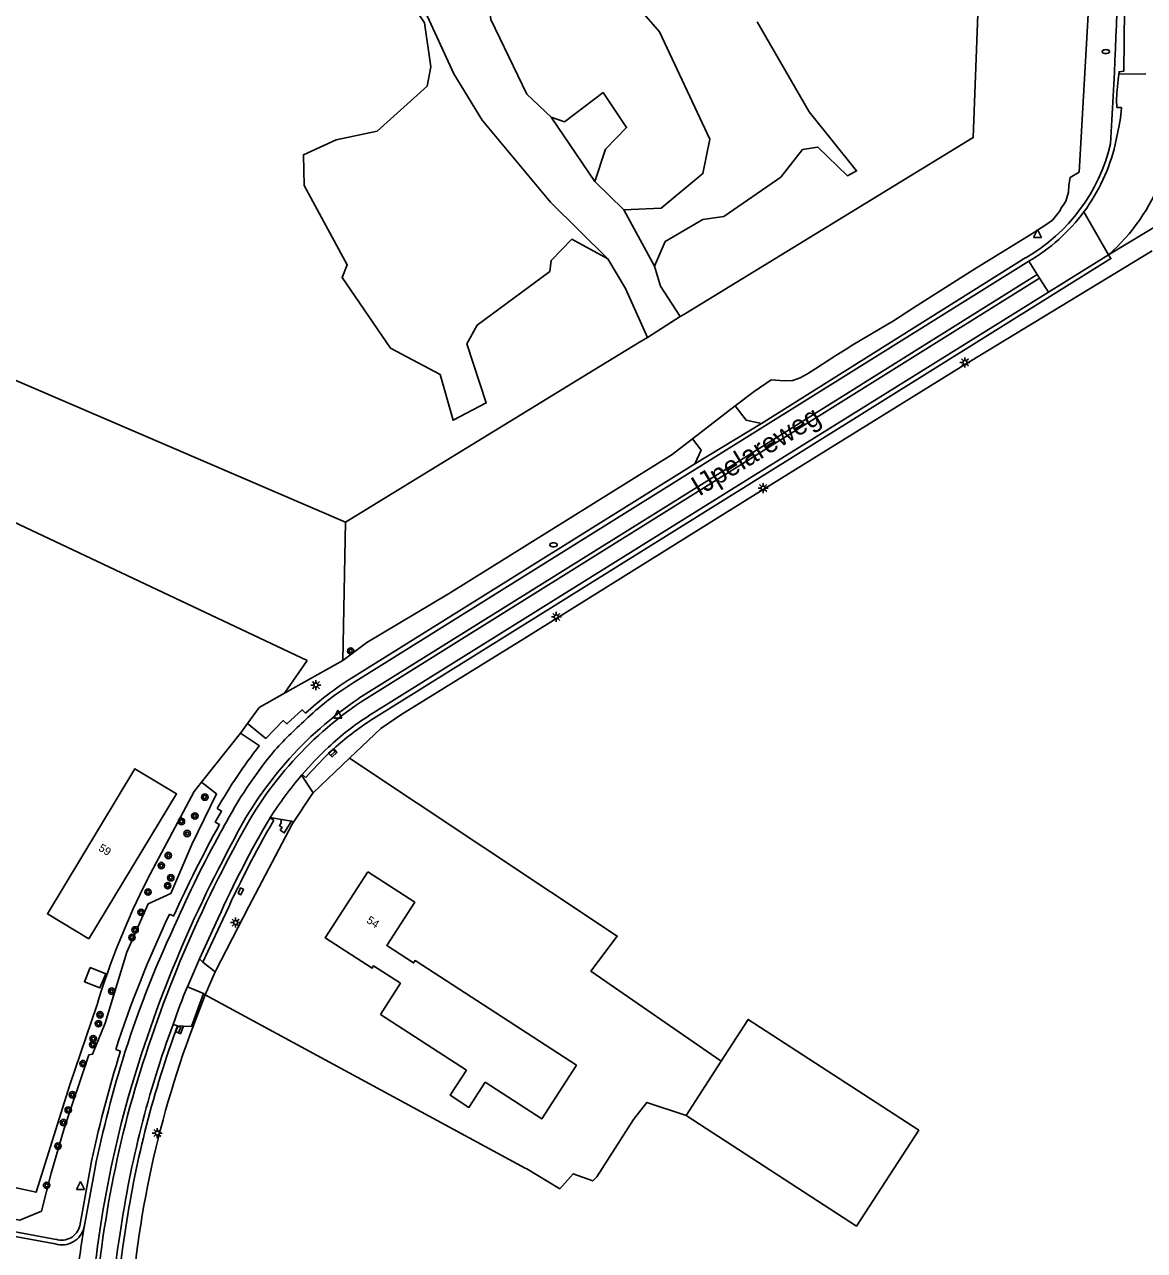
# Model space of a CAD drawing. Extents: x 130998 to 133001, y 398999 to 403002.
# Drawn here: x 132708.1 to 132848, y 400223.9 to 400377.1 of the extents above; entities that cross this region are included whole.
import ezdxf

# ---------------------------------------------------------------- set-up
doc = ezdxf.new("R2010")
doc.units = 0
for name, color, linetype in [('gg-afsc-draadraster', 7, 'Continuous'), ('gg-afsc-hekwerk', 7, 'Continuous'), ('gg-anno-huisnummerreeks BGT', 7, 'Continuous'), ('gg-anno-openbare ruimte label', 7, 'Continuous'), ('gg-bbg-bijgebouw', 7, 'Continuous'), ('gg-bbg-hoofdgebouw', 7, 'Continuous'), ('gg-bbg-lage trafo', 7, 'Continuous'), ('gg-knt-bronhoudergrens', 7, 'Continuous'), ('gg-knt-verharding', 7, 'Continuous'), ('gg-knt-verharding nz', 7, 'Continuous'), ('gt-grn-groengrens', 7, 'Continuous'), ('gt-grn-groengrens NZ', 7, 'Continuous'), ('gt-grn-weggrens', 7, 'Continuous'), ('gt-symb-boom', 7, 'Continuous'), ('gt-symb-brandkraan', 7, 'Continuous'), ('gt-symb-kolk center center', 7, 'Continuous'), ('gt-symb-lichtmast', 7, 'Continuous'), ('gt-symb-waterafsluiter', 7, 'Continuous'), ('gx-grn-maaiveld', 7, 'Continuous')]:
    doc.layers.add(name, color=color, linetype=linetype)

# ---------------------------------------------------------------- blocks, each defined once
blk = doc.blocks.new('gt0-BR')
at = {"layer": 'gt-symb-brandkraan'}
for centre, radius, start, end in [((-0.24, 0), 0.206, 107.5669, 252.4331), ((0.6, -2.66), 3, 106.892, 107.5669), ((0, -0.69), 0.938, 73.108, 106.892), ((-0.6, -2.66), 3, 72.4331, 73.108), ((0.24, 0), 0.206, 287.567, 72.4331), ((0.6, 2.66), 3, 252.4331, 253.108), ((0, 0.69), 0.938, 253.108, 286.8921), ((-0.6, 2.66), 3, 286.8921, 287.567)]:
    blk.add_arc(centre, radius, start, end, dxfattribs=at)
blk = doc.blocks.new('gt0-WAFSL')
at = {"layer": 'gt-symb-waterafsluiter'}
for p, q in [((-0.5, -0.33), (0, 0.67)), ((0, 0.67), (0.5, -0.33)), ((0.5, -0.33), (-0.5, -0.33))]:
    blk.add_line(p, q, dxfattribs=at)
blk = doc.blocks.new('gt0-LMAST')
at = {"layer": 'gt-symb-lichtmast'}
for p, q in [((-0.18, 0.17), (-0.45, 0.44)), ((-0.01, 0.25), (-0.01, 0.62)), ((0.17, 0.17), (0.44, 0.44)), ((-0.26, 0), (-0.63, 0)), ((-0.18, -0.18), (-0.45, -0.45)), ((-0.01, -0.25), (-0.01, -0.63)), ((0.44, -0.45), (0.17, -0.18)), ((0.24, 0), (0.62, 0))]:
    blk.add_line(p, q, dxfattribs=at)
blk.add_circle((-0.01, 0), 0.25, dxfattribs=at)
blk = doc.blocks.new('gt0-BOOM')
at = {"layer": 'gt-symb-boom'}
for radius in [0.4, 0.2]:
    blk.add_circle((0, 0), radius, dxfattribs=at)
blk = doc.blocks.new('gt0-KOLKCC')
at = {"layer": 'gt-symb-kolk center center'}
blk.add_lwpolyline([(-0.38, 0.2), (0.38, 0.2), (0.38, -0.2), (-0.38, -0.2)], close=True, dxfattribs=at)

msp = doc.modelspace()

# ---------------------------------------------------------------- linework, layer by layer
at = {"layer": 'gg-afsc-draadraster'}
for p, q in [((132723.58, 400267.23), (132720.93, 400261.2)), ((132730.7, 400255.89), (132770.67, 400234.22))]:
    msp.add_line(p, q, dxfattribs=at)
msp.add_lwpolyline([(132716.16, 400248.4), (132713.1, 400239.2), (132711.45, 400233.59)], dxfattribs=at)
at = {"layer": 'gg-afsc-hekwerk'}
for p, q in [((132790.02, 400340.59), (132790.44, 400340.85)), ((132790.44, 400340.85), (132790.68, 400341)), ((132785.91, 400338), (132790.02, 400340.59)), ((132784.92, 400337.39), (132785.91, 400338)), ((132748.21, 400314.9), (132747.89, 400297.62)), ((132747.89, 400297.62), (132740.6, 400293.54)), ((132735.09, 400288.58), (132730.23, 400282.43)), ((132736, 400289.76), (132735.09, 400288.58)), ((132744.2, 400281.1), (132748.73, 400285.43)), ((132744.2, 400281.1), (132748.73, 400285.43)), ((132741.57, 400277.2), (132741.72, 400277.43)), ((132730.7, 400255.89), (132731.95, 400258.77)), ((132731.95, 400258.77), (132731.98, 400258.82)), ((132731.95, 400258.77), (132731.98, 400258.82)), ((132729.16, 400251.86), (132730.7, 400255.89))]:
    msp.add_line(p, q, dxfattribs=at)
for points in [[(132790.68, 400341), (132826.6, 400362.96), (132827.23, 400380.57), (132827.91, 400408.15), (132828.73, 400450.46), (132829.65, 400488.45), (132829.78, 400500)], [(132304.6, 400411.08), (132314.42, 400407.28), (132377.15, 400382.53), (132500, 400333.94), (132615.12, 400288.56), (132631.4, 400323.33), (132647.49, 400358.16), (132670.06, 400348.42), (132709.01, 400331.76), (132748.21, 400314.9)], [(132748.73, 400285.43), (132752.61, 400289.13), (132755.12, 400290.84), (132770.59, 400300.42), (132798.51, 400317.83), (132825.1, 400334.33), (132848.92, 400348.8)], [(132748.73, 400285.43), (132752.61, 400289.13), (132755.12, 400290.84), (132770.59, 400300.42), (132798.51, 400317.83), (132825.1, 400334.33), (132848.92, 400348.8)], [(132748.21, 400314.9), (132779.25, 400333.95), (132784.92, 400337.39)], [(132740.6, 400293.54), (132737.44, 400291.77), (132736, 400289.76)], [(132730.23, 400282.43), (132729.32, 400281.28), (132723.54, 400270.39)], [(132741.72, 400277.43), (132744.02, 400280.92), (132744.2, 400281.1)], [(132731.98, 400258.82), (132736.15, 400266.9), (132741.57, 400277.2)], [(132731.98, 400258.82), (132736.15, 400266.9), (132741.57, 400277.2)], [(132658.24, 400242.36), (132709.58, 400231.22), (132713.79, 400244.64), (132717.15, 400254.53)]]:
    msp.add_lwpolyline(points, dxfattribs=at)
for centre, radius, start, end in [((132810.4, 400226.22), 97.45, 153.0479, 163.1141), ((132846.27, 400207.76), 125.13, 159.3647, 177.2216)]:
    msp.add_arc(centre, radius, start, end, dxfattribs=at)
at = {"layer": 'gg-bbg-bijgebouw'}
msp.add_line((132790.75, 400240.8), (132795.13, 400247.58), dxfattribs=at)
msp.add_lwpolyline([(132795.13, 400247.58), (132798.5, 400252.81), (132819.8, 400238.97), (132812.01, 400226.99), (132790.75, 400240.8)], dxfattribs=at)
at = {"layer": 'gg-bbg-hoofdgebouw'}
msp.add_line((132763.31, 400246.49), (132752.57, 400253.44), dxfattribs=at)
for points in [[(132716.17, 400262.86), (132727.1, 400280.99), (132721.93, 400284.11), (132711.01, 400265.98), (132716.17, 400262.86)], [(132751, 400271.26), (132745.66, 400263.01), (132751.54, 400259.21), (132751.72, 400259.49), (132755.08, 400257.32), (132752.57, 400253.44)], [(132751, 400271.26), (132756.87, 400267.45), (132753.37, 400262.05), (132756.72, 400259.87), (132756.91, 400260.16), (132777.04, 400247.09), (132772.71, 400240.39), (132765.66, 400244.96)], [(132763.31, 400246.49), (132761.28, 400243.35), (132763.62, 400241.82), (132765.66, 400244.96)]]:
    msp.add_lwpolyline(points, dxfattribs=at)
at = {"layer": 'gg-bbg-lage trafo'}
msp.add_lwpolyline([(132716.35, 400259.29), (132718.28, 400258.51), (132717.56, 400256.74), (132715.63, 400257.52), (132716.35, 400259.29)], dxfattribs=at)
at = {"layer": 'gg-knt-bronhoudergrens'}
msp.add_lwpolyline([(132795.13, 400247.58), (132778.84, 400258.84), (132782.15, 400263.21), (132748.73, 400285.43)], dxfattribs=at)
at = {"layer": 'gg-knt-verharding'}
for p, q in [((132779.36, 400357.46), (132773.9, 400365.51)), ((132782.98, 400353.94), (132779.36, 400357.46)), ((132786.8, 400346.9), (132782.98, 400353.94)), ((132835.99, 400343.63), (132843.49, 400348.29)), ((132749.16, 400294.84), (132833.52, 400347.5)), ((132800.17, 400327.24), (132833.15, 400347.96)), ((132791.82, 400322.21), (132800.17, 400327.24)), ((132748.95, 400295.42), (132791.82, 400322.21)), ((132737.46, 400286.99), (132735.09, 400288.58)), ((132746.76, 400286.62), (132746.1, 400286.01)), ((132742.72, 400283.3), (132742.79, 400283.39)), ((132744.2, 400281.1), (132742.72, 400283.3)), ((132742.79, 400283.39), (132743.24, 400283.01)), ((132738.8, 400277.98), (132738.83, 400278.05)), ((132739.28, 400277.7), (132738.8, 400277.98)), ((132738.83, 400278.05), (132740.24, 400277.8)), ((132740.24, 400277.8), (132741.46, 400277.59)), ((132741.46, 400277.59), (132741.72, 400277.43)), ((132726.23, 400265.94), (132726.77, 400265.69)), ((132729.97, 400260.36), (132732.32, 400265.44)), ((132730.42, 400259.98), (132732.91, 400265.27)), ((132729.97, 400260.36), (132730.42, 400259.98)), ((132731.95, 400258.77), (132730.42, 400259.98)), ((132730.5, 400256.05), (132728.48, 400256.9)), ((132730.5, 400256.05), (132730.7, 400255.89)), ((132726.99, 400251.28), (132727.26, 400251.99)), ((132727.26, 400251.99), (132728, 400251.95)), ((132720.13, 400248.84), (132719.54, 400249.05)), ((132715.05, 400227.01), (132716.32, 400234.16)), ((132715.57, 400226.86), (132716.91, 400234.08)), ((132702.2, 400226.57), (132711.97, 400224.76))]:
    msp.add_line(p, q, dxfattribs=at)
for points in [[(132844.77, 400370.89), (132844.8, 400371.18), (132845.39, 400371.24), (132845.8, 400409.64), (132847.82, 400515.05)], [(132780.99, 400347.81), (132773.82, 400354.88), (132765.3, 400365.12), (132761.74, 400370.9), (132757.25, 400380.75), (132752.34, 400384.68), (132746.8, 400386.99), (132736.8, 400389.8), (132723.69, 400394.1), (132717.48, 400395.57), (132710.13, 400395.59)], [(132773.9, 400365.51), (132770.86, 400368.38), (132766.35, 400377.69), (132765.77, 400382.6)], [(132844.31, 400362.08), (132844.81, 400364.46), (132844.97, 400365.39), (132845.08, 400366.26), (132845.1, 400366.64), (132845.07, 400366.71), (132844.98, 400366.73), (132844.6, 400366.7), (132844.53, 400366.74), (132844.51, 400366.78), (132844.5, 400367.6), (132844.53, 400368.49), (132844.68, 400370.17), (132844.77, 400370.89)], [(132843.49, 400348.29), (132853.13, 400354.14), (132856.45, 400356.17)], [(132751.38, 400290.18), (132798.89, 400319.85), (132843.78, 400347.85), (132843.49, 400348.29)], [(132785.91, 400338), (132783.16, 400344.12), (132780.99, 400347.81)], [(132790.02, 400340.59), (132787.53, 400344.39), (132786.8, 400346.9)], [(132751.08, 400290.71), (132798.61, 400320.39), (132835.99, 400343.63)], [(132800.17, 400327.24), (132798.24, 400327.67), (132796.89, 400329.43)], [(132791.82, 400322.21), (132792.61, 400323.93), (132791.54, 400325.32)], [(132736, 400289.76), (132738.26, 400287.91), (132739.34, 400289.04), (132740.45, 400290.14), (132740.89, 400289.72), (132742.82, 400291.49), (132743.21, 400291.05)], [(132746.1, 400286.01), (132746.54, 400285.59), (132747.14, 400286.15), (132746.76, 400286.62)], [(132732.48, 400277.16), (132731.95, 400277.46), (132732.75, 400278.84), (132732.21, 400279.14)], [(132740.24, 400277.8), (132740.13, 400277.63), (132740.18, 400277.51), (132740.18, 400277.35), (132739.96, 400277), (132740.3, 400276.77), (132740.08, 400276.45), (132740.58, 400276.11), (132741.46, 400277.59)], [(132728.48, 400256.9), (132729.24, 400258.63), (132729.97, 400260.36)], [(132728, 400251.95), (132728.97, 400251.91), (132730.5, 400256.05)], [(132726.99, 400251.28), (132727.61, 400251.01), (132728, 400251.95)], [(132702.2, 400226.57), (132702.29, 400227.15), (132712.08, 400225.34)]]:
    msp.add_lwpolyline(points, dxfattribs=at)
for centre, radius, start, end in [((132011.1, 400411.9), 834.11, 356.58308, 359.85087), ((132822.01, 400367.29), 22.32, 299.9574, 346.7694), ((132821.99, 400367.32), 22.93, 323.4782, 346.7735), ((132821.99, 400367.33), 22.93, 300.1729, 323.4713), ((132770.84, 400260.68), 41.06, 122.2136, 132.289), ((132768.53, 400263.74), 36.64, 121.9229, 133.0291), ((132787.58, 400241.74), 65.73, 132.0758, 137.1598), ((132767.9, 400264.03), 31.53, 122.2292, 133.7821), ((132768.62, 400263.01), 32.17, 122.3957, 132.8014), ((132787.87, 400247.6), 63.98, 141.9938, 150.4681), ((132783.57, 400250.07), 57.22, 140.5574, 152.0901), ((132777.8, 400252.9), 46.42, 133.0914, 138.9434), ((132777.52, 400253.22), 45.41, 133.7711, 139.0042), ((132782.13, 400250), 51.59, 139.8035, 147.0636), ((132848.2, 400213.51), 126.99, 149.4898, 155.8627), ((132871.92, 400200.47), 159.14, 151.1896, 155.8043), ((132843.71, 400214.5), 127.06, 150.6064, 156.3757), ((132850.42, 400212.86), 128.67, 149.7371, 155.963), ((132855.08, 400205.14), 142.48, 154.7376, 162.0496), ((132847.66, 400208.1), 133.31, 154.5357, 162.2664), ((132788.35, 400231.55), 65.01, 157.046, 161.4994), ((132846.81, 400207.83), 128.04, 159.7353, 171.7965), ((132845.95, 400208.17), 126.54, 160.0794, 171.878), ((132862.12, 400204.22), 148.84, 162.554, 168.395), ((132870.28, 400202.29), 156.64, 162.7624, 168.2892), ((132712.8, 400227.48), 2.84, 252.9691, 347.3282), ((132712.77, 400227.59), 2.35, 252.9406, 345.6464), ((132843.92, 400206.16), 125.44, 170.8555, 185.7776), ((132842.38, 400206.18), 123.31, 170.7274, 182.7238)]:
    msp.add_arc(centre, radius, start, end, dxfattribs=at)
at = {"layer": 'gg-knt-verharding nz'}
for p, q in [((132834.57, 400345.86), (132834.85, 400345.41)), ((132726.7, 400252.18), (132727.26, 400251.99))]:
    msp.add_line(p, q, dxfattribs=at)
for points in [[(132749.89, 400292.92), (132797.19, 400322.47), (132834.57, 400345.86)], [(132834.85, 400345.41), (132797.48, 400322.02), (132750.19, 400292.49)]]:
    msp.add_lwpolyline(points, dxfattribs=at)
for centre, radius, start, end in [((132827.31, 400366.53), 24.38, 311.5685, 6.4473), ((132776.03, 400254.03), 46.85, 123.9081, 153.8904), ((132776.25, 400253.87), 46.59, 124.0074, 153.7963), ((132871.78, 400200.13), 156.68, 151.6016, 164.9244), ((132870.28, 400200.7), 154.56, 151.5027, 164.9661), ((132857.29, 400205.41), 141.32, 165.4603, 179.9283), ((132857.43, 400205.38), 140.94, 165.4481, 179.9129), ((132826.12, 400208.51), 112.06, 170.5751, 174.7636)]:
    msp.add_arc(centre, radius, start, end, dxfattribs=at)
at = {"layer": 'gt-grn-groengrens'}
for p, q in [((132841.53, 400389.22), (132839.83, 400358.63)), ((132775.56, 400364.91), (132773.9, 400365.51)), ((132787.62, 400354.13), (132782.98, 400353.94)), ((132747.89, 400297.62), (132750.89, 400299.88)), ((132740.6, 400293.54), (132743.45, 400297.66))]:
    msp.add_line(p, q, dxfattribs=at)
for points in [[(132787.62, 400354.13), (132792.84, 400358.46), (132793.71, 400362.74), (132787.41, 400376.16), (132778.8, 400386.1), (132776.02, 400386.74), (132772.19, 400385.49), (132769.8, 400383.73)], [(132750.83, 400381.61), (132755.79, 400380.79), (132758.1, 400377.27), (132758.87, 400371.81), (132758.41, 400369.36), (132752.16, 400363.75), (132747.06, 400362.66), (132742.96, 400360.81), (132743.05, 400356.96), (132748.44, 400347.08), (132747.8, 400345.49), (132753.82, 400336.66), (132760.04, 400333.37), (132761.65, 400327.65), (132765.8, 400329.82), (132763.36, 400337.19), (132764.64, 400339.53), (132773.71, 400346.22), (132773.89, 400347.58), (132776.46, 400350.25), (132780.99, 400347.81)], [(132786.8, 400346.9), (132788.15, 400349.96), (132792.84, 400352.74), (132795.44, 400353.08), (132802.58, 400358.02), (132805.28, 400361.46), (132807.2, 400361.77), (132810.9, 400358.19), (132812.03, 400358.78), (132806.09, 400366.17), (132799.6, 400377.39)], [(132779.36, 400357.46), (132780.7, 400361.49), (132783.32, 400364.2), (132780.38, 400368.57), (132775.56, 400364.91)], [(132839.83, 400358.63), (132838.7, 400357.98), (132838.51, 400357.02), (132838.48, 400356.13), (132838.27, 400355.43), (132838.17, 400355.03), (132837.87, 400354.54), (132837.59, 400354.17), (132837.44, 400353.83), (132836.55, 400352.7), (132835.89, 400352.22), (132835.07, 400351.66), (132834.23, 400351.12), (132833.38, 400350.59), (132829.57, 400348.28), (132827.02, 400346.7), (132824.49, 400345.1), (132819.15, 400341.67), (132816.62, 400340.07), (132815.03, 400339.1), (132811.58, 400337.05), (132810.73, 400336.53), (132809.45, 400335.73), (132806.95, 400334.1), (132805.89, 400333.44), (132805, 400332.96), (132804.06, 400332.62), (132803.97, 400332.61), (132802.99, 400332.55), (132801.37, 400332.71), (132799.25, 400331.25)], [(132743.45, 400297.66), (132669.19, 400332.68), (132643.9, 400313.85), (132626.15, 400270.16)], [(132789, 400323.37), (132761.09, 400305.95), (132750.89, 400299.88)], [(132730.23, 400282.43), (132732.13, 400280.98), (132729.04, 400274.65), (132726.43, 400268.55), (132723.58, 400267.23)], [(132720.93, 400261.2), (132718.22, 400252.36), (132716.64, 400248.46), (132716.16, 400248.4)], [(132658.24, 400242.36), (132657.35, 400237.86), (132674.21, 400233.16), (132686.43, 400231.66), (132697.86, 400229.52), (132707.57, 400227.75), (132710.26, 400228.87), (132711.45, 400233.59)]]:
    msp.add_lwpolyline(points, dxfattribs=at)
at = {"layer": 'gt-grn-groengrens NZ'}
for p, q in [((132796.89, 400329.43), (132799.25, 400331.25)), ((132791.54, 400325.32), (132796.89, 400329.43)), ((132789, 400323.37), (132791.54, 400325.32))]:
    msp.add_line(p, q, dxfattribs=at)
at = {"layer": 'gt-grn-weggrens'}
for p, q in [((132848.13, 400370.9), (132844.77, 400370.89)), ((132840.42, 400353.68), (132843.49, 400348.29)), ((132834.57, 400345.86), (132833.52, 400347.5)), ((132834.85, 400345.41), (132835.99, 400343.63))]:
    msp.add_line(p, q, dxfattribs=at)
at = {"layer": 'gx-grn-maaiveld'}
msp.add_lwpolyline([(132790.75, 400240.8), (132785.82, 400242.44), (132784.16, 400240.3), (132779.58, 400233.15), (132779.1, 400232.65), (132776.66, 400233.53), (132774.99, 400231.67), (132770.86, 400234.16), (132770.67, 400234.22)], dxfattribs=at)

# ---------------------------------------------------------------- block references
at = {"layer": 'gt-symb-boom'}
for p in [(132748.87, 400298.82), (132730.65, 400280.58), (132727.73, 400277.54), (132729.41, 400278.22), (132728.45, 400276.03), (132726.09, 400273.28), (132725.22, 400272.02), (132726.4, 400270.5), (132723.56, 400268.72), (132726.02, 400269.51), (132722.7, 400266.19), (132721.95, 400263.99), (132721.56, 400263.05), (132719.03, 400256.34), (132717.57, 400253.38), (132717.37, 400252.28), (132716.72, 400250.41), (132716.66, 400249.66), (132715.44, 400247.29), (132714.12, 400243.39), (132713.6, 400241.49), (132713.01, 400239.92), (132712.32, 400236.99), (132710.9, 400232.09)]:
    msp.add_blockref('gt0-BOOM', p, dxfattribs=at)
at = {"layer": 'gt-symb-brandkraan'}
for p in [(132843.15, 400373.69), (132774.19, 400312.09)]:
    msp.add_blockref('gt0-BR', p, dxfattribs=at)
at = {"layer": 'gt-symb-kolk center center'}
for p, rotation in [((132746.53, 400286.16), 42.785559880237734), ((132735.14, 400268.8), 66.15713994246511), ((132727.34, 400251.55), 68.26602725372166)]:
    msp.add_blockref('gt0-KOLKCC', p, dxfattribs=dict(at, rotation=rotation))
at = {"layer": 'gt-symb-lichtmast'}
for p in [(132825.56, 400334.88), (132800.37, 400319.18), (132774.55, 400303.08), (132744.53, 400294.57), (132734.5, 400264.9), (132724.72, 400238.62)]:
    msp.add_blockref('gt0-LMAST', p, dxfattribs=at)
at = {"layer": 'gt-symb-waterafsluiter'}
for p in [(132834.61, 400350.81), (132747.26, 400290.77), (132715.12, 400231.91)]:
    msp.add_blockref('gt0-WAFSL', p, dxfattribs=at)

# ---------------------------------------------------------------- texts
at = {"layer": 'gg-anno-huisnummerreeks BGT'}
for s, rotation, p in [('59', 328.9, (132717.29, 400273.96)), ('54', 327.1, (132750.76, 400264.96))]:
    msp.add_text(s, height=1, rotation=rotation, dxfattribs=at).set_placement(p)
at = {"layer": 'gg-anno-openbare ruimte label'}
msp.add_text('IJpelareweg', height=2.5, rotation=31.2, dxfattribs=at).set_placement((132792.36, 400318.09))

doc.saveas('drawing.dxf')
